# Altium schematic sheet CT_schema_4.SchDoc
size 283 x 147 mm
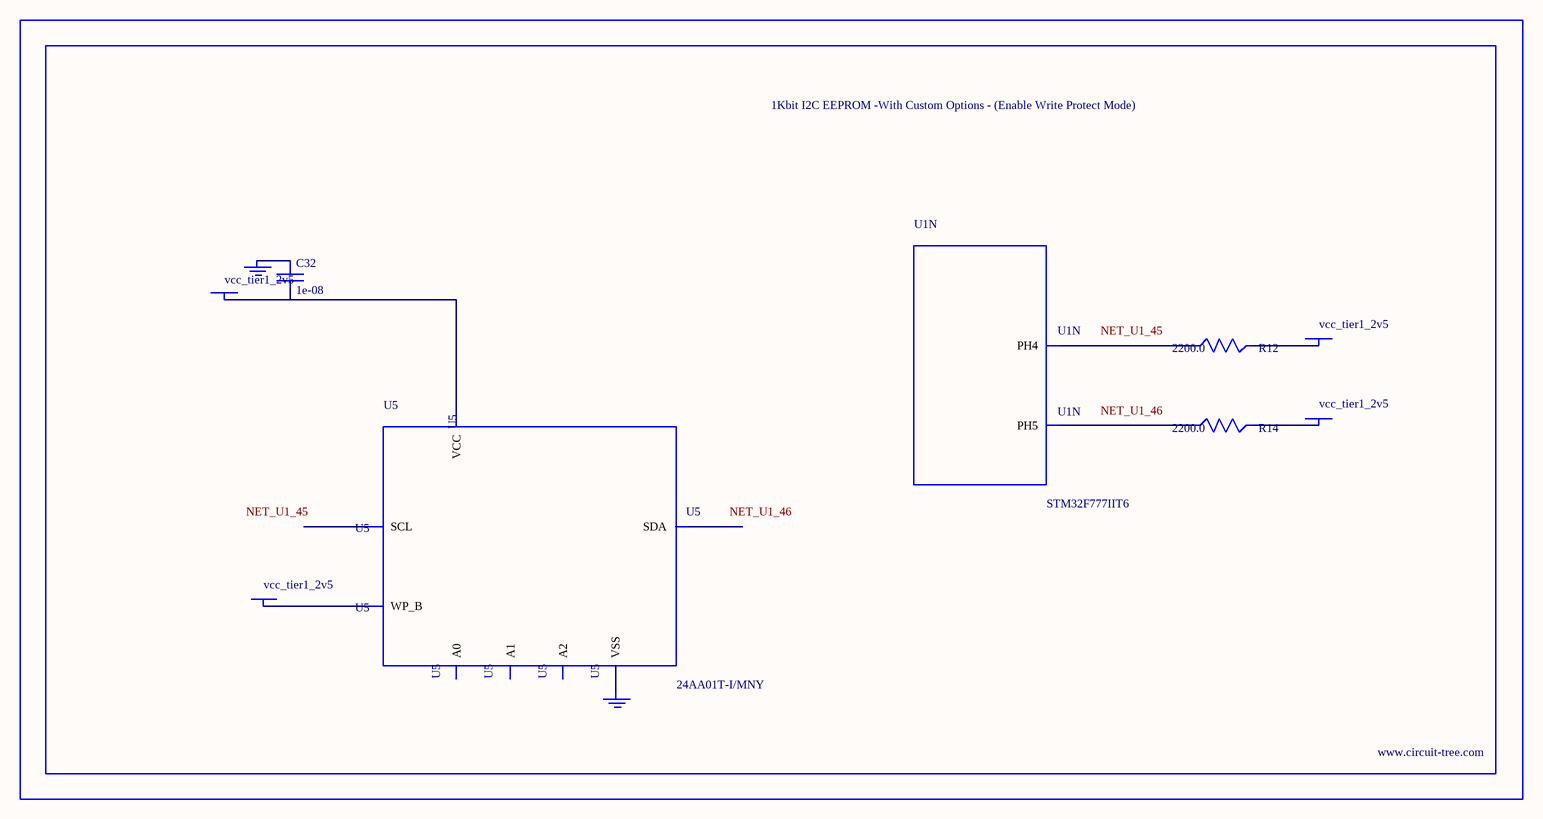
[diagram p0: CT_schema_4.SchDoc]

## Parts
BORDER3  (no value)
C32  1e-08  [C0402]
GND_INSTANCE_3_0  (no value)
GND_INSTANCE_3_1  (no value)
POWER_INSTANCE_3_0  vcc_tier1_2v5
POWER_INSTANCE_3_1  vcc_tier1_2v5
POWER_INSTANCE_3_2  vcc_tier1_2v5
POWER_INSTANCE_3_3  vcc_tier1_2v5
R12  2200.0  [R0603]
R14  2200.0  [R0603]
U1  STM32F777IIT6  [LQFP176]  (part N of 15)
U5  24AA01T-I/MNY  [TDFN-8/6MM]

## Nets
NetC32_1: C32.1 GND_INSTANCE_3_0.0(GND)
NetC32_2: C32.2 POWER_INSTANCE_3_1.0(PWR) U5.8(VCC)
NetGND_INSTANCE_3_1_0: GND_INSTANCE_3_1.0(GND) U5.4(VSS)
NetPOWER_INSTANCE_3_0_0: POWER_INSTANCE_3_0.0(PWR) U5.7(WP_B)
NetPOWER_INSTANCE_3_2_0: POWER_INSTANCE_3_2.0(PWR) R12.2
NetPOWER_INSTANCE_3_3_0: POWER_INSTANCE_3_3.0(PWR) R14.2
NetR12_1: R12.1 U1.45(PH4)
NetR14_1: R14.1 U1.46(PH5)

Not connected (* = marked no-connect by the designer): U5 1(A0) 2(A1) 3(A2) 5(SDA) 6(SCL)

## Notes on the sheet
- Labels drawn without touching a wire or pin: NET_U1_45, NET_U1_46

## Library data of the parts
BORDER3 = BORDER_PAGE3
C32 = C0402C103K3RAC
GND_INSTANCE_3_0 GND_INSTANCE_3_1 = GND
POWER_INSTANCE_3_0-POWER_INSTANCE_3_3 = PWR
R12 R14 = RC0603JR-072K2L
